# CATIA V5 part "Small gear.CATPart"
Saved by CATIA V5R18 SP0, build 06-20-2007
Part number: Part3
Bounding box of the stored display mesh (mm): x -20 to 20, y -20 to 20, z 0 to 10
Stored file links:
  D:\shriniwas\v5_r19\c16_CAT_v5r19\c16_Part\Gear Joint\Small gear.CATPart
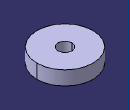
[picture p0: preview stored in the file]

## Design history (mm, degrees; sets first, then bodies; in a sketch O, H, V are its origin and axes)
Body1 (main body)
  Sketch1 on xy-plane, origin (0, 0, 0), H (1, 0, 0), V (0, 1, 0)
    circle A1 centre (0, 0) radius 20
    circle A2 centre (0, 0) radius 5
    radius A1 = 20
    radius A2 = 5
  Pad1: profile Sketch1, direction (0, 0, 1), length 10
